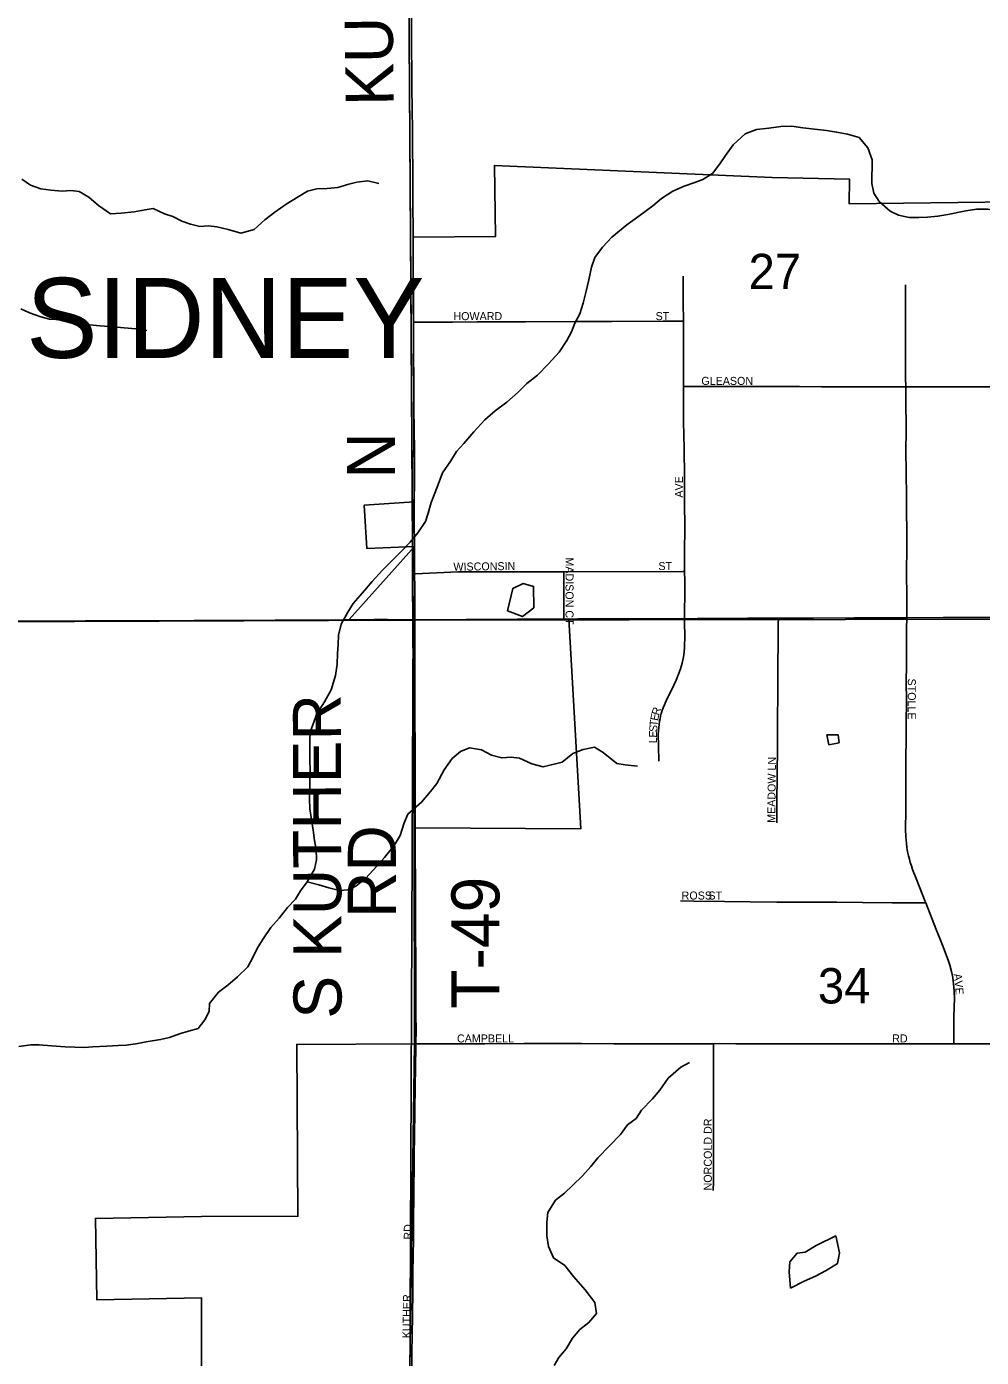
# Model space of a CAD drawing. Extents: x 0 to 1391, y -24 to 440.
# Drawn here: x 438.04 to 460.63, y 332.13 to 363.63 of the extents above; entities that cross this region are included whole.
import ezdxf

# ---------------------------------------------------------------- set-up
doc = ezdxf.new("R2010")
doc.units = 0
for name, color, linetype in [('GM_X_City_Street', 7, 'Continuous'), ('GM_X_City_Street_Text', 7, 'Continuous'), ('GM_X_Corporation', 7, 'Continuous'), ('GM_X_Corporation_Text', 7, 'Continuous'), ('GM_X_Minor_Lake', 7, 'Continuous'), ('GM_X_Minor_River', 7, 'Continuous'), ('GM_X_Section', 7, 'Continuous'), ('GM_X_Section_Text', 7, 'Continuous'), ('GM_X_State_Route', 7, 'Continuous'), ('GM_X_Township', 7, 'Continuous'), ('GM_X_Township_Road', 7, 'Continuous'), ('GM_X_Township_Road_Text', 7, 'Continuous')]:
    doc.layers.add(name, color=color, linetype=linetype)

msp = doc.modelspace()

# ---------------------------------------------------------------- linework, layer by layer
at = {"layer": 'GM_X_City_Street'}
for points in [[(453.583, 356.653), (453.577, 357.095), (453.575, 357.719)], [(458.843, 355.102), (458.842, 355.323), (458.842, 356.28), (458.842, 356.628), (458.839, 357.513)], [(447.191, 356.631), (447.255, 356.631), (448.12, 356.633), (448.704, 356.637), (449.847, 356.639), (451.04, 356.648), (451.885, 356.648), (453.102, 356.656), (453.548, 356.653), (453.583, 356.653)], [(453.584, 355.107), (453.584, 355.728), (453.583, 356.187), (453.584, 356.548), (453.583, 356.653)], [(453.584, 355.107), (453.609, 355.107), (455.225, 355.112), (455.585, 355.112), (455.932, 355.11), (456.33, 355.107), (456.852, 355.105), (457.56, 355.101), (458.255, 355.105), (458.843, 355.102)], [(453.611, 350.734), (453.608, 351.193), (453.614, 351.764), (453.612, 352.373), (453.606, 352.97), (453.598, 353.641), (453.587, 354.274), (453.584, 354.61), (453.584, 355.107)], [(458.843, 355.102), (458.876, 355.102), (459.472, 355.101), (459.87, 355.099), (461.596, 355.101), (462.18, 355.101), (462.913, 355.1), (463.047, 355.1)], [(458.866, 349.635), (458.868, 350.141), (458.865, 350.688), (458.866, 351.321), (458.86, 352.514), (458.847, 353.621), (458.851, 354.031), (458.844, 354.876), (458.843, 355.102)], [(447.219, 350.672), (447.24, 350.673), (448.242, 350.72), (450.749, 350.726), (450.749, 350.726)], [(450.749, 350.726), (453.574, 350.734), (453.611, 350.734)], [(450.755, 349.606), (450.755, 349.627), (450.749, 350.716), (450.749, 350.726)], [(453.61, 349.612), (453.607, 349.777), (453.615, 350.199), (453.613, 350.498), (453.611, 350.734)], [(452.999, 346.241), (452.99, 346.601), (452.987, 346.881), (453, 347.041), (453.006, 347.105), (453.02, 347.187), (453.03, 347.244), (453.044, 347.308), (453.059, 347.37), (453.081, 347.438), (453.104, 347.504), (453.132, 347.577), (453.191, 347.712), (453.297, 347.923), (453.411, 348.158), (453.469, 348.297), (453.515, 348.427), (453.552, 348.559), (453.584, 348.707), (453.599, 348.819), (453.608, 348.943), (453.613, 349.205), (453.612, 349.516), (453.61, 349.612)], [(455.793, 344.778), (455.796, 344.949), (455.797, 345.246), (455.806, 346.587), (455.807, 346.773), (455.81, 347.332), (455.814, 347.741), (455.816, 348.114), (455.816, 348.412), (455.823, 349.156), (455.828, 349.494), (455.829, 349.624)], [(459.318, 342.885), (459.305, 342.917), (459.089, 343.46), (459.006, 343.68), (458.978, 343.761), (458.952, 343.844), (458.931, 343.918), (458.911, 343.999), (458.896, 344.061), (458.88, 344.143), (458.87, 344.207), (458.86, 344.291), (458.852, 344.369), (458.846, 344.45), (458.841, 344.623), (458.848, 345.083), (458.847, 345.295), (458.846, 346.003), (458.854, 347.071), (458.859, 347.742), (458.858, 348.066), (458.859, 348.575), (458.865, 349.37), (458.866, 349.635)], [(453.51, 342.935), (453.832, 342.926), (454.553, 342.918), (455.162, 342.909), (455.796, 342.906), (456.344, 342.901), (456.692, 342.902), (457.214, 342.901), (457.823, 342.894), (458.519, 342.889), (459.263, 342.885), (459.318, 342.885)], [(459.98, 339.55), (459.98, 339.65), (459.982, 340.158), (459.991, 340.431), (459.995, 340.618), (459.989, 340.793), (459.976, 340.967), (459.968, 341.032), (459.955, 341.116), (459.926, 341.263), (459.889, 341.409), (459.85, 341.528), (459.711, 341.888), (459.618, 342.118), (459.564, 342.258), (459.318, 342.885)], [(447.146, 330.858), (447.152, 331.613), (447.156, 332.234), (447.163, 332.644), (447.173, 333.128), (447.177, 333.687), (447.18, 334.147), (447.193, 334.929), (447.194, 335.438), (447.202, 335.898), (447.214, 336.891), (447.215, 337.401), (447.225, 337.935), (447.236, 338.581), (447.242, 338.941), (447.254, 339.55)], [(447.254, 339.55), (448.212, 339.553), (448.883, 339.553), (449.815, 339.554), (450.659, 339.554), (451.169, 339.554), (451.939, 339.548), (453.518, 339.55), (454.293, 339.553)], [(454.289, 336.077), (454.291, 336.288), (454.292, 337.018), (454.292, 337.355), (454.293, 337.701), (454.293, 338.103), (454.294, 338.445), (454.292, 338.906), (454.292, 339.378), (454.293, 339.553)], [(454.293, 339.553), (454.425, 339.554), (454.823, 339.553), (455.468, 339.552), (456.426, 339.553), (457.072, 339.549), (457.37, 339.546), (458.525, 339.549), (458.923, 339.552), (459.283, 339.551), (459.979, 339.55), (459.98, 339.55)], [(459.98, 339.55), (460.352, 339.55), (460.948, 339.551), (461.483, 339.549), (461.906, 339.546), (462.489, 339.542), (463.234, 339.548), (464.689, 339.549), (465.111, 339.548), (465.608, 339.547), (466.962, 339.551), (467.41, 339.554), (467.761, 339.554)]]:
    msp.add_lwpolyline(points, dxfattribs=at)
at = {"layer": 'GM_X_Corporation'}
msp.add_lwpolyline([(467.788, 359.563), (457.506, 359.432), (457.515, 360.015), (455.683, 360.059), (449.11, 360.344), (449.137, 358.664), (447.184, 358.641), (447.191, 356.631), (447.211, 352.378), (446.028, 352.298), (446.09, 351.277), (447.216, 351.323), (445.674, 349.594), (447.224, 349.59), (450.87, 349.607), (451.155, 344.641), (447.238, 344.666), (447.22, 339.546), (444.433, 339.534), (444.461, 335.467), (442.175, 335.462), (439.668, 335.416), (439.703, 333.489), (442.179, 333.534), (442.187, 329.348)], dxfattribs=at)
at = {"layer": 'GM_X_Minor_Lake'}
for p, q in [((456.976, 346.866), (457.025, 346.63)), ((457.268, 346.678), (457.242, 346.861))]:
    msp.add_line(p, q, dxfattribs=at)
for points in [[(450.043, 349.867), (450.037, 350.379), (449.788, 350.445), (449.542, 350.328), (449.423, 349.796)], [(449.423, 349.796), (449.774, 349.664), (450.043, 349.867)], [(457.242, 346.861), (456.976, 346.866)], [(457.025, 346.63), (457.268, 346.678)], [(457.188, 335.007), (456.724, 334.773), (456.463, 334.619), (456.272, 334.592), (456.102, 334.391), (456.082, 334.149), (456.115, 333.769)], [(456.115, 333.769), (456.443, 333.93), (456.711, 334.046), (456.964, 334.184), (457.226, 334.346), (457.276, 334.602), (457.188, 335.007)]]:
    msp.add_lwpolyline(points, dxfattribs=at)
at = {"layer": 'GM_X_Minor_River'}
for points in [[(441.661, 339.784), (441.868, 339.849), (442.097, 339.914), (442.26, 340.116), (442.363, 340.311), (442.366, 340.501), (442.583, 340.77), (442.8, 340.941), (443.031, 341.134), (443.271, 341.373), (443.404, 341.606), (443.499, 341.809), (443.624, 342.012), (443.82, 342.305), (444.013, 342.522), (444.216, 342.776), (444.402, 342.97), (444.519, 343.173), (444.675, 343.383), (444.855, 343.683), (444.897, 343.903), (444.893, 344.146), (444.851, 344.359), (444.817, 344.61), (444.742, 345.112), (444.73, 345.347), (444.738, 345.795), (444.749, 346.038), (444.745, 346.258), (444.742, 346.501), (444.738, 346.728), (444.749, 346.926), (444.908, 347.363), (445.088, 347.648), (445.245, 347.927), (445.35, 348.266), (445.385, 348.539), (445.396, 348.789), (445.415, 349.001), (445.419, 349.221), (445.484, 349.486), (445.641, 349.764), (445.766, 349.974), (445.991, 350.229), (446.216, 350.491), (446.464, 350.76), (446.689, 350.991), (446.898, 351.193), (447.115, 351.424), (447.294, 351.649), (447.481, 351.911), (447.545, 352.108), (447.61, 352.365), (447.697, 352.583), (447.777, 352.787), (447.88, 353.066), (448.075, 353.351), (448.216, 353.569), (448.387, 353.763), (448.619, 354.033), (448.883, 354.317), (449.13, 354.533), (449.4, 354.741), (449.67, 354.979), (449.879, 355.181), (450.126, 355.381), (450.389, 355.65), (450.645, 355.919), (450.824, 356.197), (450.934, 356.4), (451.014, 356.611), (451.132, 356.83), (451.212, 357.079), (451.278, 357.366), (451.343, 357.638), (451.409, 357.933), (451.489, 358.167), (451.668, 358.407), (451.885, 358.647), (452.24, 358.937), (452.525, 359.145), (452.856, 359.39), (453.064, 359.561), (453.333, 359.731), (453.602, 359.855), (453.832, 359.928), (454.046, 360.007), (454.269, 360.148), (454.448, 360.38), (454.581, 360.576), (454.76, 360.831), (455.046, 361.092), (455.314, 361.193), (455.604, 361.227), (455.886, 361.267), (456.145, 361.271), (456.411, 361.236), (456.753, 361.192), (456.965, 361.166), (457.208, 361.131), (457.466, 361.082)], [(457.466, 361.082), (457.739, 361.001), (457.948, 360.762), (458.05, 360.472), (458.041, 359.918), (458.091, 359.689), (458.217, 359.49), (458.472, 359.258), (458.676, 359.163), (458.927, 359.114), (459.155, 359.11), (459.361, 359.122), (459.605, 359.14), (459.841, 359.182), (460.269, 359.266), (460.521, 359.307), (460.78, 359.311), (461, 359.269), (461.227, 359.166), (461.475, 359.01), (461.671, 358.893), (461.89, 358.768), (462.155, 358.673), (462.368, 358.669)], [(437.925, 360.018), (438.129, 359.879), (438.372, 359.786), (438.616, 359.76), (438.882, 359.734), (439.088, 359.747), (439.285, 359.722), (439.512, 359.591), (439.739, 359.391), (440.027, 359.198), (440.278, 359.21), (440.583, 359.245), (440.842, 359.295), (441.033, 359.323), (441.306, 359.198), (441.503, 359.136), (441.715, 359.027), (441.92, 358.956), (442.14, 358.901), (442.346, 358.914), (442.544, 358.889), (442.81, 358.825), (443.106, 358.738), (443.426, 358.825), (443.68, 359.058), (443.917, 359.237), (444.178, 359.424), (444.469, 359.602), (444.683, 359.736), (444.904, 359.787), (445.148, 359.799), (445.407, 359.819), (445.667, 359.9), (445.857, 359.943), (446.116, 359.978), (446.375, 359.914)], [(437.905, 356.948), (438.11, 356.854), (438.376, 356.76), (438.581, 356.705), (438.87, 356.686), (439.06, 356.669), (439.303, 356.621), (439.531, 356.573), (439.782, 356.547), (440.086, 356.521), (440.345, 356.495), (440.626, 356.477), (440.885, 356.436)], [(444.675, 343.383), (444.956, 343.317), (445.19, 343.245), (445.441, 343.18), (445.639, 343.192), (445.83, 343.28), (446.07, 343.473), (446.318, 343.75), (446.512, 343.959), (446.737, 344.243), (446.878, 344.484), (446.974, 344.778), (447.062, 344.989), (447.386, 345.272), (447.596, 345.519), (447.744, 345.714), (447.917, 346.037), (448.111, 346.307), (448.304, 346.471), (448.519, 346.558), (448.807, 346.508), (449.041, 346.383), (449.284, 346.318), (449.505, 346.337), (449.703, 346.311), (449.997, 346.177), (450.263, 346.104), (450.714, 346.218), (450.968, 346.419), (451.213, 346.513), (451.481, 346.569), (451.684, 346.445), (452.007, 346.189), (452.205, 346.155), (452.493, 346.12)], [(437.857, 339.485), (438.139, 339.526), (438.337, 339.523), (438.626, 339.503), (438.953, 339.482), (439.181, 339.47), (439.41, 339.466), (439.6, 339.478), (439.936, 339.495), (440.202, 339.513), (440.393, 339.518), (440.668, 339.559), (440.866, 339.593), (441.21, 339.648), (441.424, 339.697), (441.661, 339.784)], [(450.522, 331.933), (450.632, 332.128), (450.81, 332.33), (450.959, 332.578), (451.13, 332.787), (451.346, 332.951), (451.525, 333.168), (451.483, 333.426), (451.26, 333.726), (450.983, 334.042), (450.775, 334.303), (450.511, 334.482), (450.386, 334.75), (450.352, 335.001), (450.35, 335.327), (450.377, 335.554), (450.557, 335.847), (450.772, 336.011), (450.966, 336.205), (451.191, 336.428), (451.392, 336.645), (451.555, 336.847), (451.834, 337.131), (452.09, 337.4), (452.261, 337.632), (452.462, 337.781), (452.594, 337.983), (452.85, 338.245), (453.021, 338.454), (453.224, 338.739), (453.525, 339), (453.725, 339.11)]]:
    msp.add_lwpolyline(points, dxfattribs=at)
at = {"layer": 'GM_X_Section'}
for points in [[(447.056, 369.114), (447.184, 349.582), (427.145, 349.502), (426.829, 369.053)], [(467.874, 369.141), (467.652, 349.609), (447.184, 349.582), (447.056, 369.114)], [(447.184, 349.582), (447.102, 329.433), (427.403, 329.248), (427.145, 349.502)], [(467.652, 349.609), (467.641, 329.557), (447.102, 329.433), (447.184, 349.582)]]:
    msp.add_lwpolyline(points, close=True, dxfattribs=at)
at = {"layer": 'GM_X_State_Route'}
for points in [[(424.188, 349.458), (425.268, 349.468), (426.026, 349.474), (426.933, 349.488), (427.188, 349.49), (429.43, 349.501), (430.86, 349.512), (431.754, 349.521), (432.587, 349.529), (433.395, 349.529), (433.966, 349.534), (434.55, 349.542), (435.134, 349.541), (436.104, 349.546), (436.899, 349.553), (437.247, 349.557), (439.434, 349.563), (440.167, 349.561), (440.726, 349.564), (442.006, 349.57), (442.951, 349.572), (443.92, 349.576), (444.118, 349.577)], [(444.118, 349.577), (444.417, 349.579), (445.519, 349.589), (445.59, 349.59)], [(445.59, 349.59), (446.264, 349.596), (446.581, 349.598), (447.192, 349.59)], [(447.192, 349.59), (447.224, 349.59)], [(447.224, 349.59), (449.362, 349.592), (450.755, 349.606), (451.081, 349.607)], [(451.081, 349.607), (453.111, 349.609), (453.61, 349.612), (453.915, 349.614), (455.111, 349.624), (455.829, 349.624), (456.658, 349.623), (457.623, 349.632), (457.907, 349.633)], [(457.907, 349.633), (458.837, 349.635), (458.866, 349.635), (459.733, 349.639), (460.155, 349.638), (461.347, 349.644), (462.181, 349.644), (462.653, 349.643), (462.971, 349.643)]]:
    msp.add_lwpolyline(points, dxfattribs=at)
at = {"layer": 'GM_X_Township'}
for points in [[(366.961, 368.979), (366.895, 354.384), (366.863, 348.93), (366.886, 328.586), (407.375, 328.93), (427.17, 329.098), (437.196, 329.183), (447.101, 329.514), (447.1, 329.807), (447.095, 330.76), (447.22, 339.546), (447.212, 344.406), (447.181, 349.555), (447.172, 350.472), (447.169, 351.314), (447.12, 358.688), (447.049, 369.139)], [(447.049, 369.139), (447.12, 358.688), (447.169, 351.314), (447.172, 350.472), (447.181, 349.555), (447.212, 344.406), (447.22, 339.546), (447.095, 330.76)]]:
    msp.add_lwpolyline(points, dxfattribs=at)
at = {"layer": 'GM_X_Township_Road'}
for points in [[(447.184, 358.641), (447.183, 359.571), (447.176, 360.304), (447.171, 360.69), (447.17, 361.1), (447.16, 361.747), (447.158, 362.12), (447.158, 362.555), (447.151, 363.127), (447.144, 363.636), (447.139, 364.146), (447.134, 364.544), (447.12, 365.227), (447.114, 366.061), (447.111, 366.533), (447.108, 366.869), (447.108, 367.291), (447.1, 367.987), (447.098, 368.718), (447.101, 369.123)], [(447.191, 356.631), (447.188, 357.006), (447.19, 357.603), (447.185, 358.224), (447.184, 358.641)], [(447.219, 350.672), (447.216, 350.948), (447.214, 352.31), (447.215, 352.943), (447.216, 353.254), (447.218, 353.614), (447.21, 354.073), (447.201, 354.608), (447.199, 355.142), (447.197, 355.577), (447.192, 356.149), (447.192, 356.509), (447.191, 356.631)], [(447.224, 349.59), (447.223, 350.334), (447.219, 350.672)], [(447.237, 344.666), (447.233, 345.521), (447.233, 346.129), (447.232, 346.762), (447.228, 347.085), (447.223, 347.42), (447.228, 347.954), (447.227, 348.55), (447.224, 349.59)], [(447.254, 339.55), (447.255, 339.879), (447.25, 340.227), (447.25, 340.65), (447.251, 341.185), (447.25, 341.583), (447.243, 342.105), (447.239, 342.515), (447.239, 343.348), (447.237, 344.044), (447.237, 344.666)]]:
    msp.add_lwpolyline(points, dxfattribs=at)

# ---------------------------------------------------------------- texts
at = {"layer": 'GM_X_City_Street_Text'}
for s, height, rotation, p in [('HOWARD', 0.1894, 0, (448.14, 356.681)), ('ST', 0.1894, 0, (452.924, 356.681)), ('GLEASON', 0.1894, 0, (454.007, 355.148)), ('AVE', 0.1894, 90, (453.571, 352.479)), ('WISCONSIN', 0.1894, 0.7444, (448.141, 350.748)), ('MADISON CT', 0.1894, 270, (450.793, 351.063)), ('ST', 0.1894, 0, (452.99, 350.765)), ('STOLLE', 0.1894, 270, (458.893, 348.196)), ('R', 0.189, 72.5402, (453.005, 347.311)), ('T', 0.189, 84.2541, (452.967, 347.057)), ('E', 0.189, 78.6418, (452.98, 347.185)), ('E', 0.189, 88.4696, (452.955, 346.795)), ('S', 0.189, 86.2822, (452.959, 346.926)), ('L', 0.189, 89.6175, (452.955, 346.662)), ('MEADOW LN', 0.1894, 89.3425, (455.755, 344.779)), ('ROSS', 0.1894, 0, (453.54, 342.965)), ('ST', 0.1894, 0, (454.174, 342.965)), ('A', 0.189, 278.0034, (459.976, 341.201)), ('V', 0.189, 275.6932, (459.998, 341.038)), ('E', 0.189, 273.9649, (460.015, 340.874)), ('CAMPBELL', 0.1894, 0, (448.224, 339.582)), ('RD', 0.1894, 0, (458.524, 339.582)), ('NORCOLD DR', 0.1894, 90, (454.255, 336.079)), ('RD', 0.1894, 90, (447.155, 334.913)), ('KUTHER', 0.1894, 89.1335, (447.121, 332.578))]:
    msp.add_text(s, height=height, rotation=rotation, dxfattribs=at).set_placement(p)
at = {"layer": 'GM_X_Corporation_Text'}
msp.add_text('SIDNEY', height=1.8939, rotation=0, dxfattribs=at).set_placement((438.028, 355.787))
at = {"layer": 'GM_X_Section_Text'}
for s, p in [('27', (455.124, 357.414)), ('34', (456.765, 340.505))]:
    msp.add_text(s, height=0.8371, rotation=0, dxfattribs=at).set_placement(p)
at = {"layer": 'GM_X_Township_Road_Text'}
for s, height, rotation, p in [('KUTHER', 1.1364, 90.6547, (446.726, 361.757)), ('N', 1.136, 90, (446.76, 352.929)), ('S KUTHER', 1.1364, 90.1414, (445.493, 340.146)), ('RD', 1.1364, 90, (446.777, 342.529)), ('T-49', 1.1364, 90, (449.229, 340.379))]:
    msp.add_text(s, height=height, rotation=rotation, dxfattribs=at).set_placement(p)

doc.saveas('drawing.dxf')
